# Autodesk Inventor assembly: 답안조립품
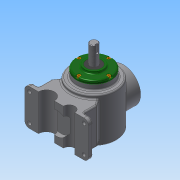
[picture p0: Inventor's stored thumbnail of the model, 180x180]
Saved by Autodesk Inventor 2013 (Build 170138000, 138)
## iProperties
Created: 2018-08
Part Number: 답안조립품
Document SubType Name: Assembly
Designer: user
Author: user
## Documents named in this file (10)
- C:\Users\user\Desktop\480808V1010\답안조립품.iam
- C:\Users\user\Desktop\480808V1010\답안조립품.ipt
- C:\Users\user\Desktop\480808V1010\메인 축.ipt
- 메인 축.ipt
- C:\Users\user\Desktop\480808V1010\메인 베벨기어.ipt
- C:\Users\user\Desktop\480808V1010\베어링 6203.ipt
- C:\Users\user\Desktop\480808V1010\키 5x5.ipt
- C:\Users\user\Desktop\480808V1010\커버.ipt
- C:\Users\user\Desktop\480808V1010\오일실 17 32 8.ipt
- C:\Users\user\Desktop\480808V1010\볼트 M4.ipt
